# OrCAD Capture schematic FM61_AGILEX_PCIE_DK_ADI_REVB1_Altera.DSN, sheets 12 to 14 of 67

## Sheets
12 DDR4 Single DIMM CH1: size B
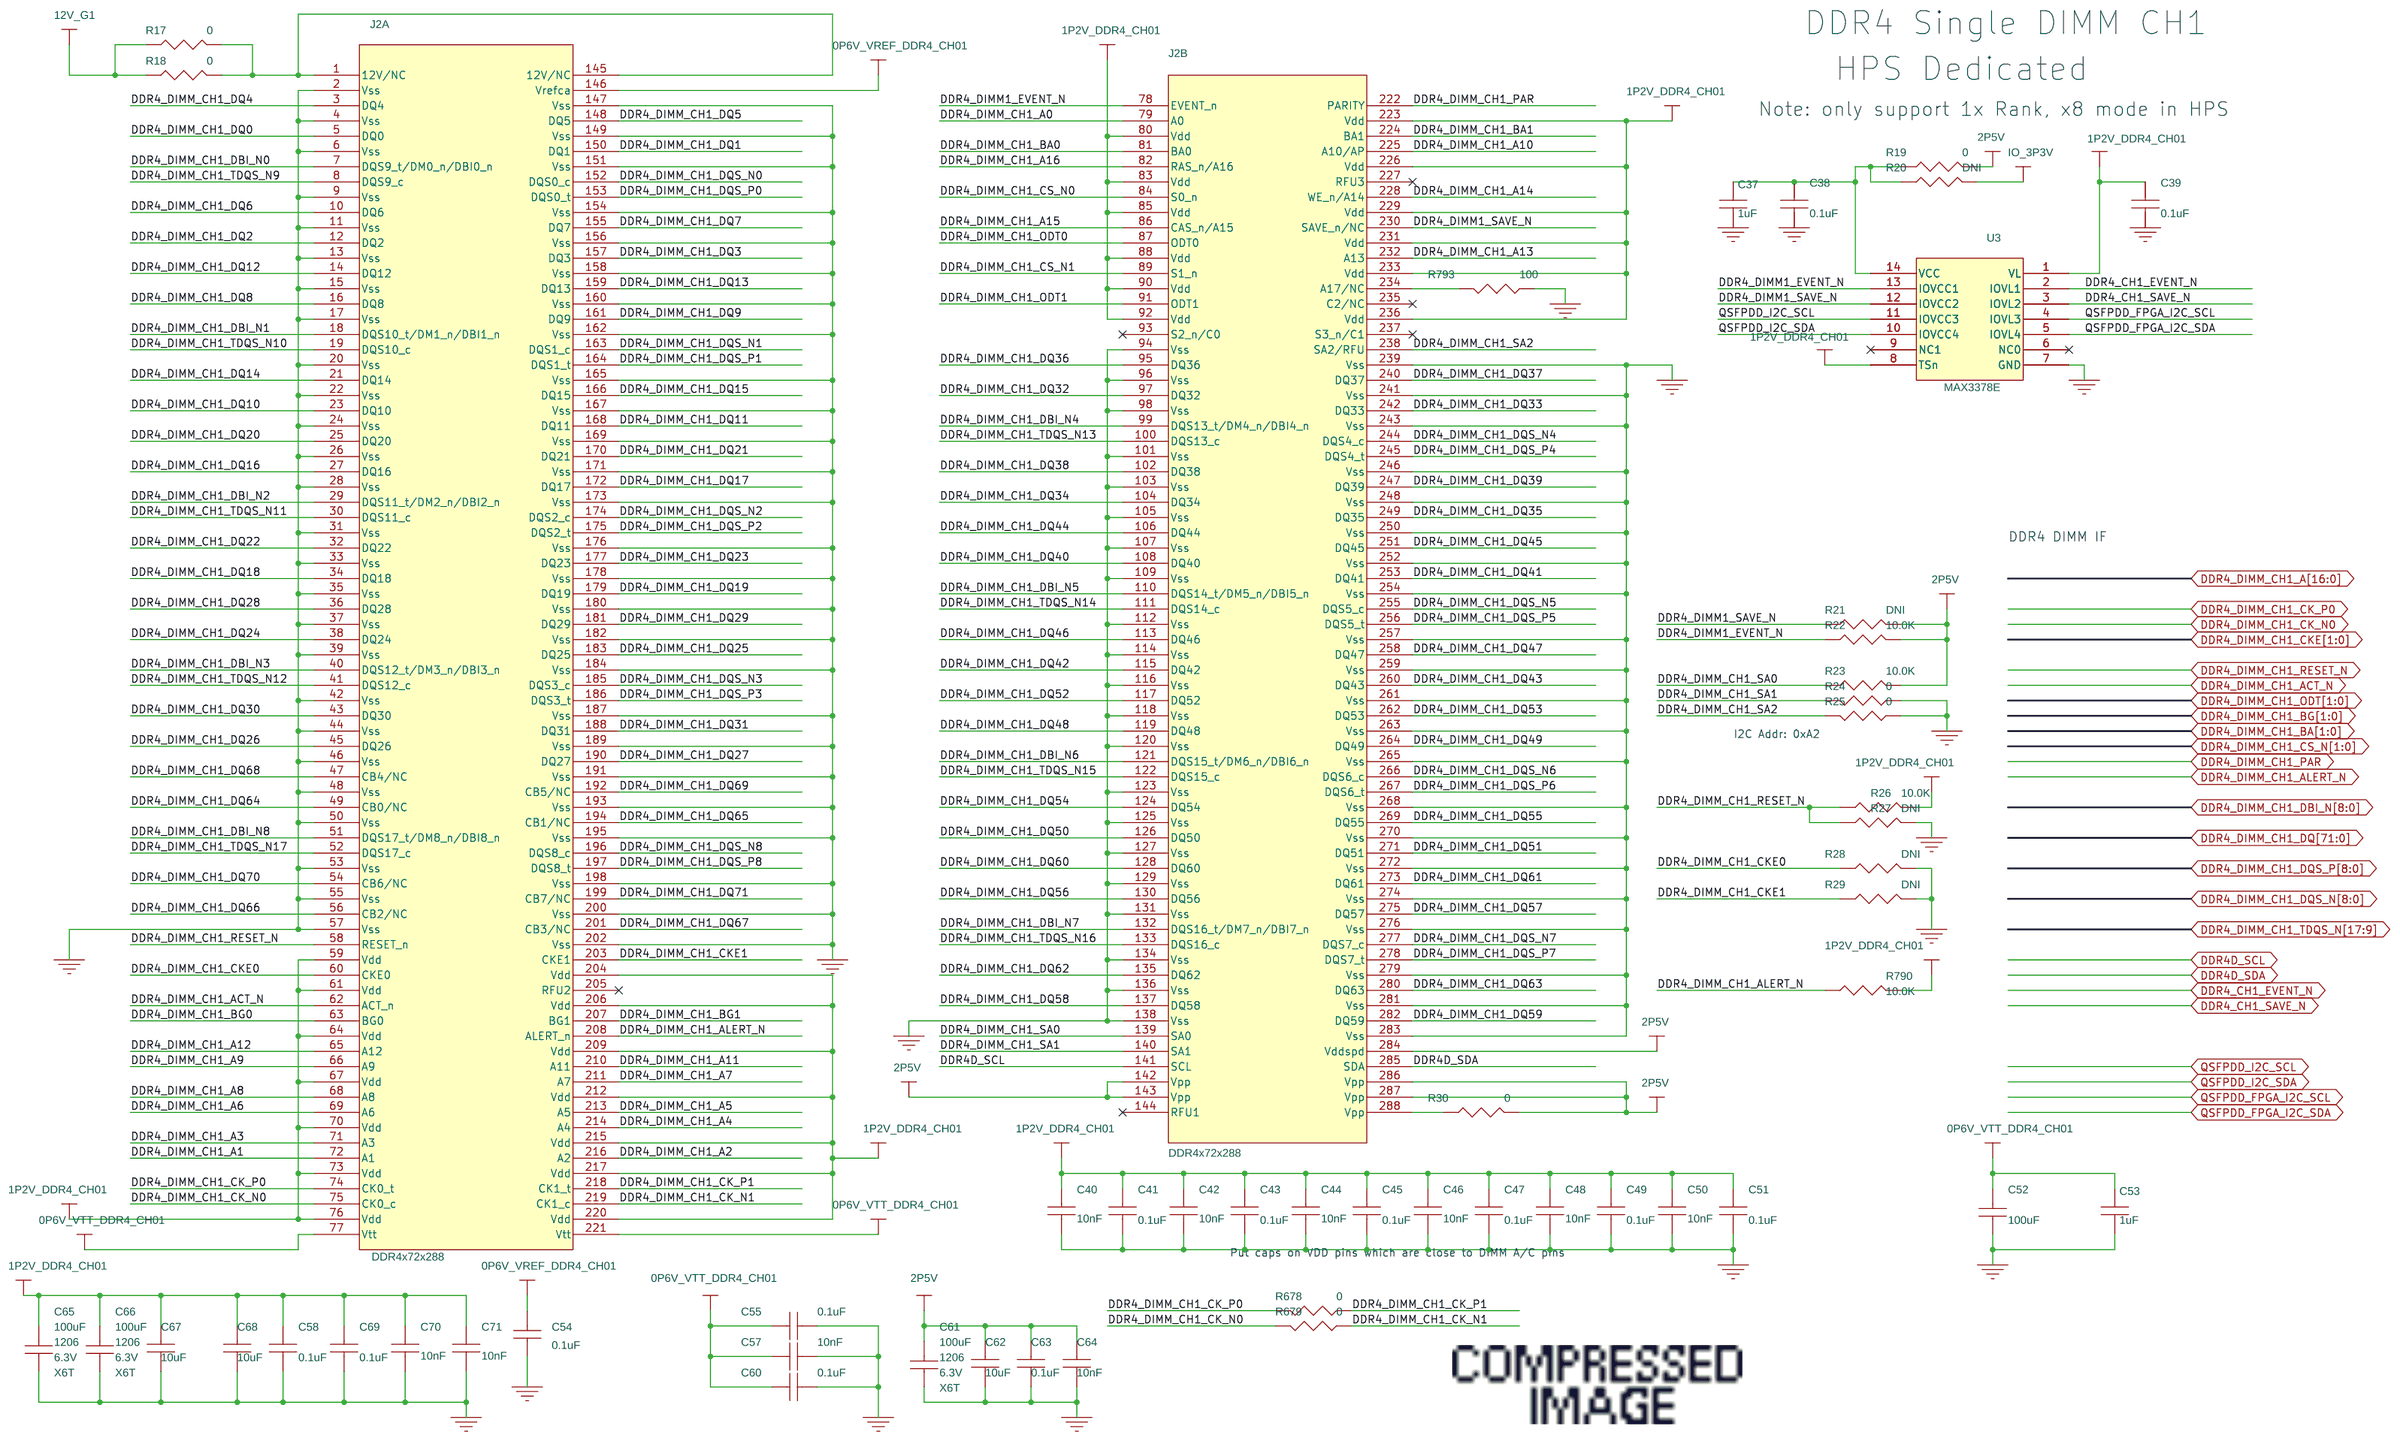
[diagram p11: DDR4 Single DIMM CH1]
13 FPGA BANK 3C: size B
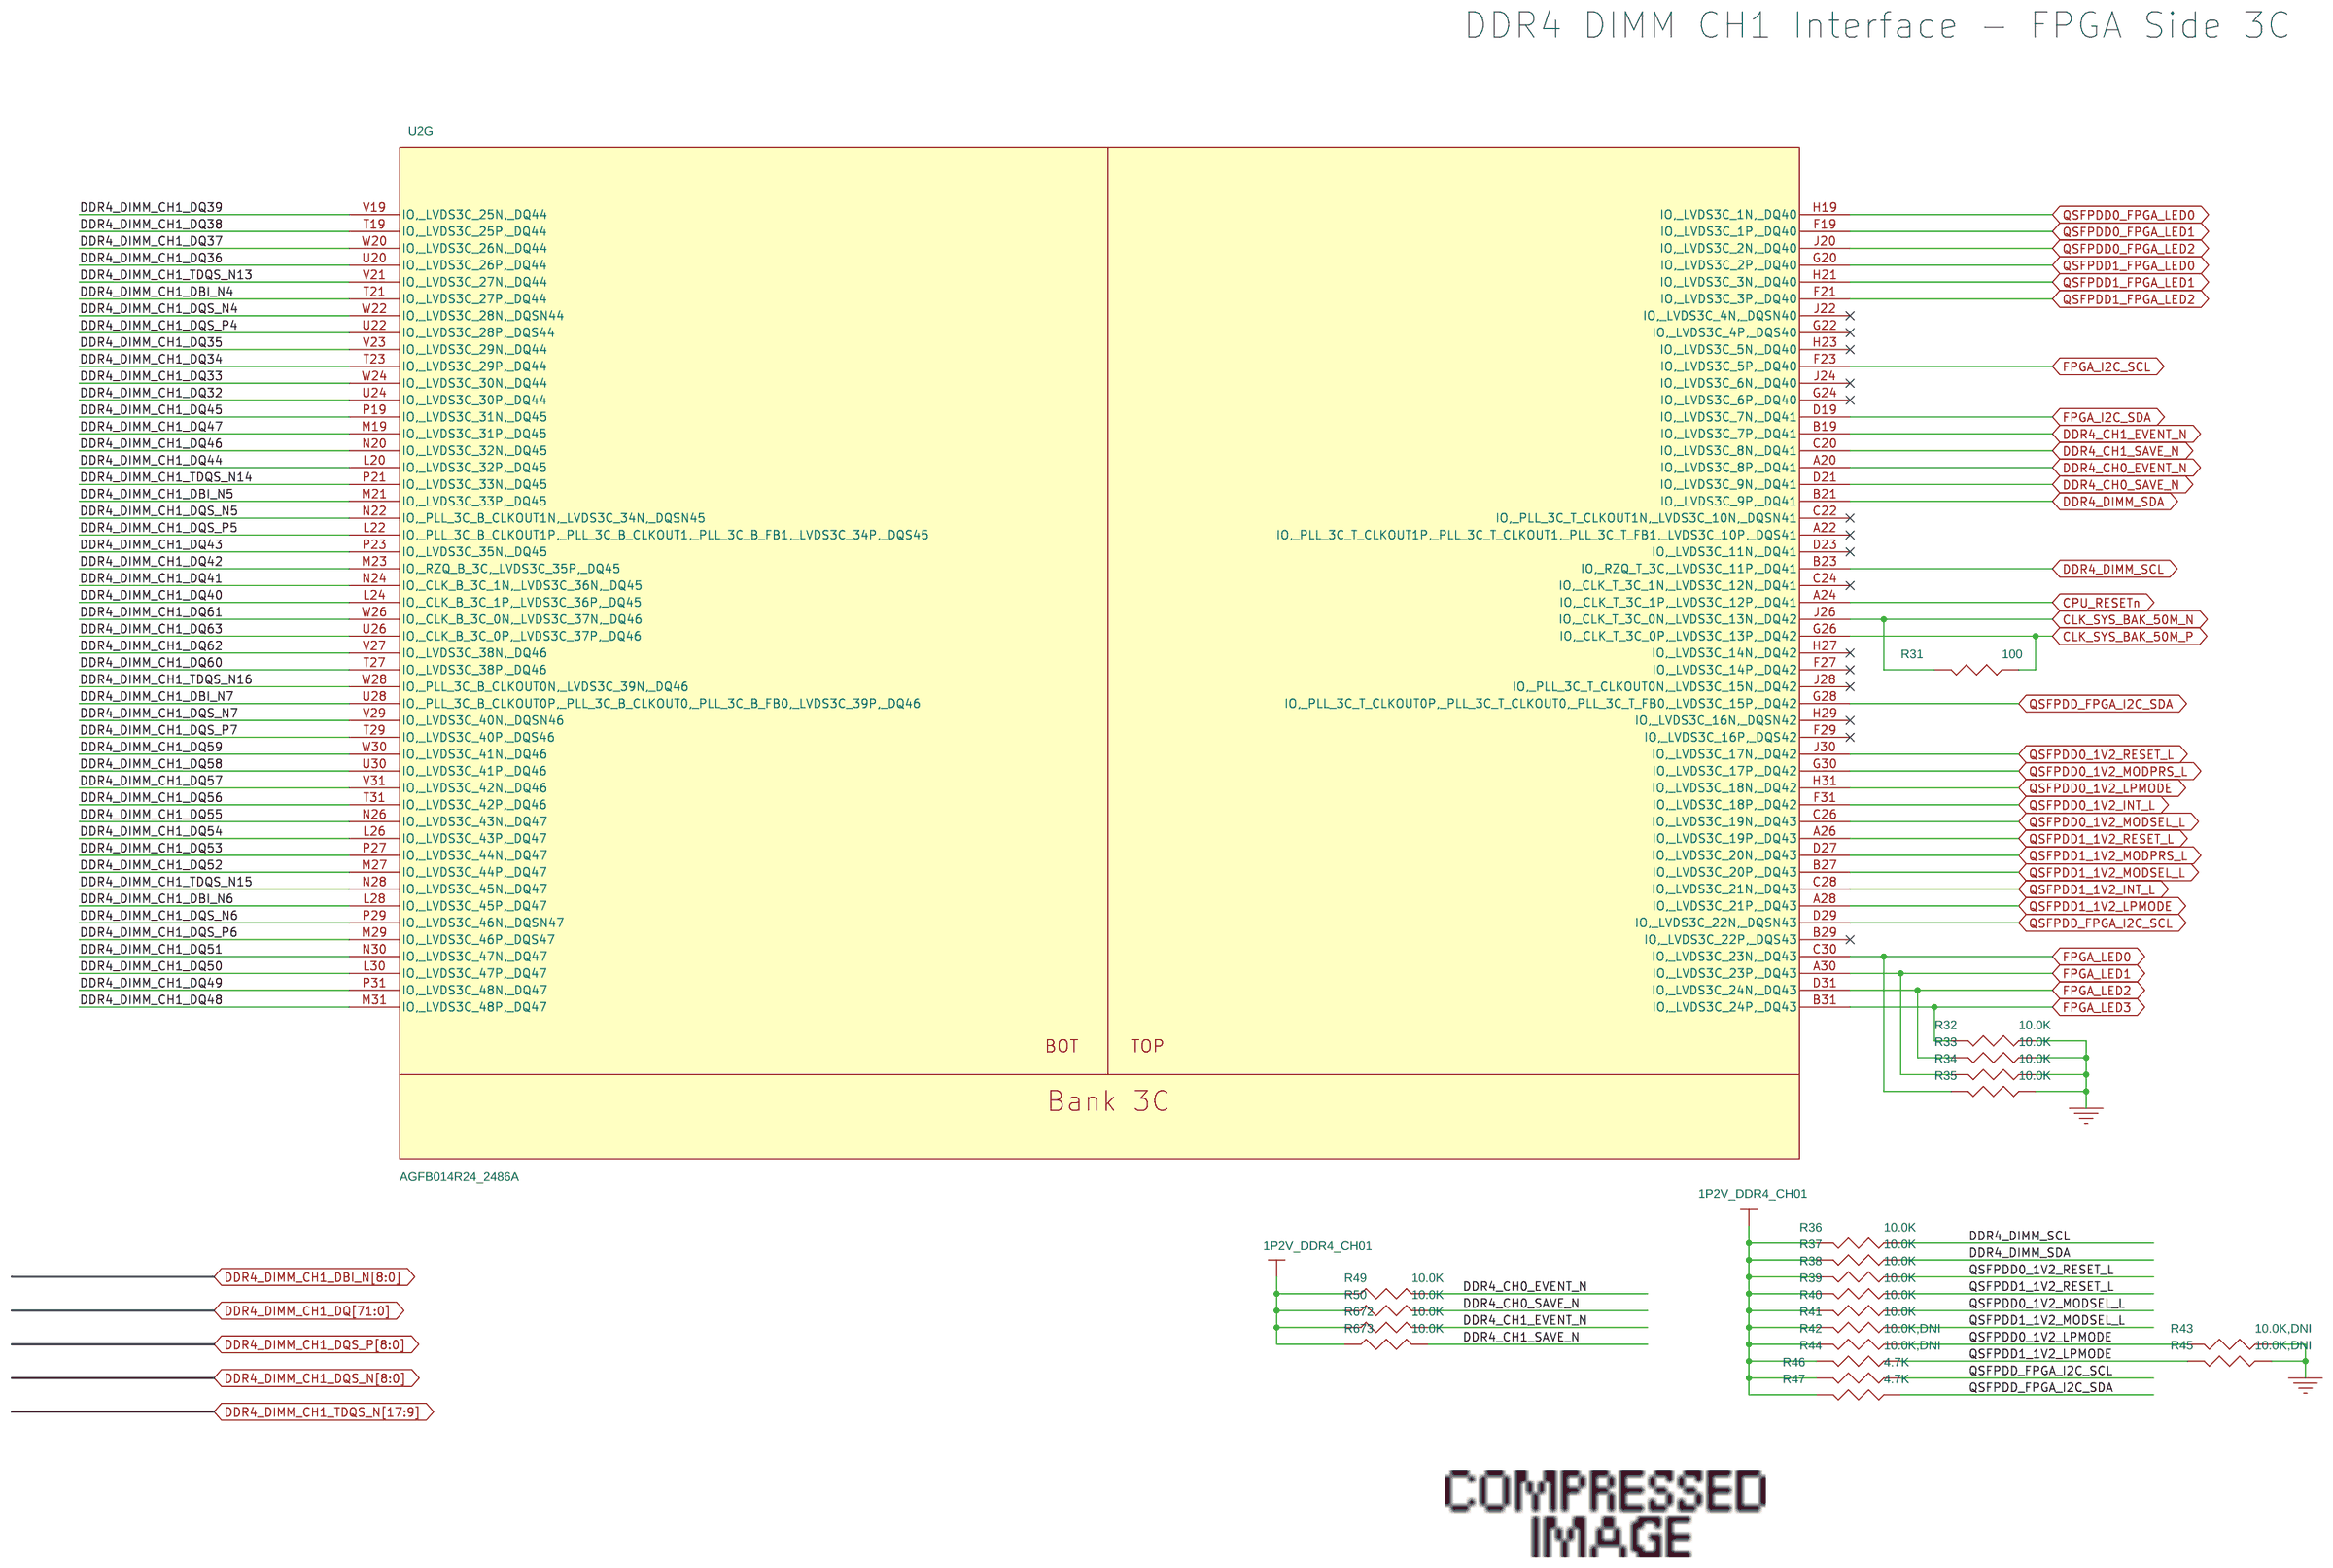
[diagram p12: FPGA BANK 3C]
14 FPGA BANK 3D: size B
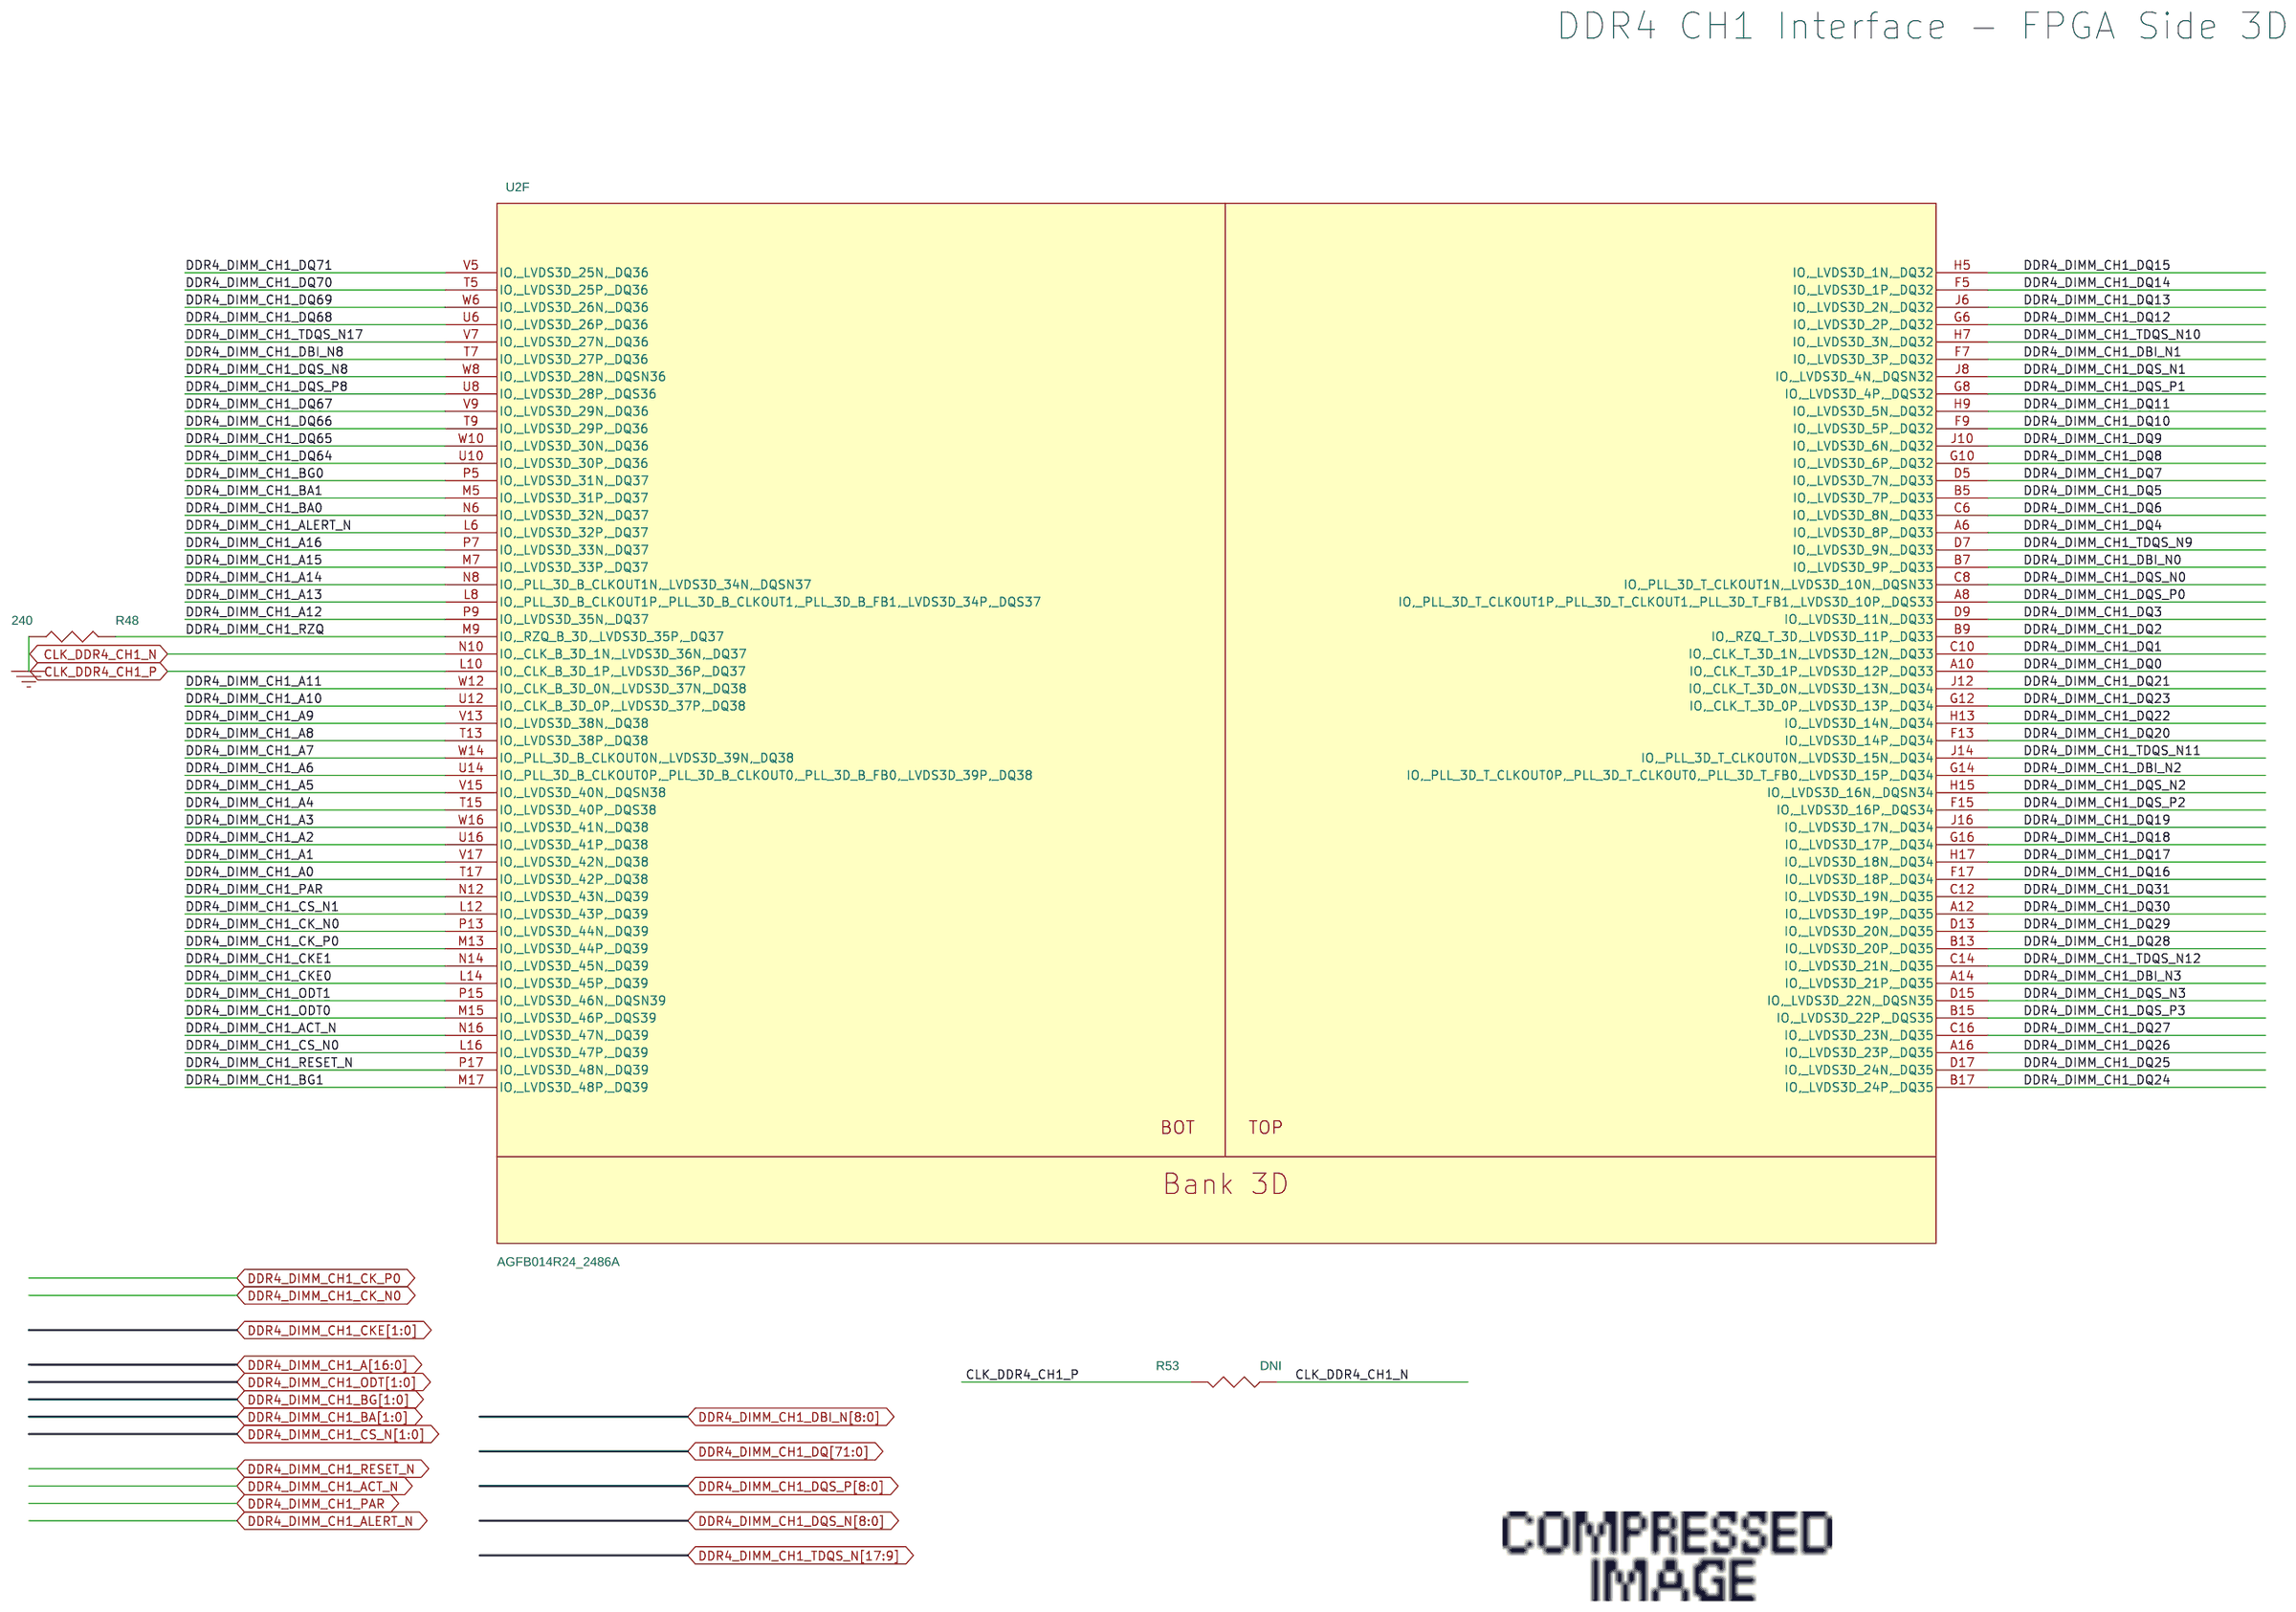
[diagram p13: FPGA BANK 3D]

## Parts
sheet DDR4 Single DIMM CH1
C37  1uF  [0402]
C38  0.1uF  [0402]
C39  0.1uF  [0402]
C40  10nF  [0402]
C41  0.1uF  [0402]
C42  10nF  [0402]
C43  0.1uF  [0402]
C44  10nF  [0402]
C45  0.1uF  [0402]
C46  10nF  [0402]
C47  0.1uF  [0402]
C48  10nF  [0402]
C49  0.1uF  [0402]
C50  10nF  [0402]
C51  0.1uF  [0402]
C52  100uF  [1206]
C53  1uF  [0402]
C54  0.1uF  [0402]
C55  0.1uF  [0402]
C57  10nF  [0402]
C58  0.1uF  [0402]
C60  0.1uF  [0402]
C61  100uF  [1206]
C62  10uF  [1210]
C63  0.1uF  [0402]
C64  10nF  [0402]
C65  100uF  [1206]
C66  100uF  [1206]
C67  10uF  [1210]
C68  10uF  [1210]
C69  0.1uF  [0402]
C70  10nF  [0402]
C71  10nF  [0402]
J2  DDR4x72x288  [DDR4DIMM_SMT]  (sections A,B)
R17  0  [1206]
R18  0  [1206]
R19  0  [0603]
R20  DNI  [0603]
R21  DNI  [0402]
R22  10.0K  [0402]
R23  10.0K  [0402]
R24  0  [0402]
R25  0  [0402]
R26  10.0K  [0402]
R27  DNI  [0402]
R28  DNI  [0402]
R29  DNI  [0402]
R30  0  [0603]
R678  0  [0402]
R679  0  [0402]
R790  10.0K  [0402]
R793  100  [0402]
U3  MAX3378E  [TSSOP-14]
sheet FPGA BANK 3C
R31  100  [0402]
R32  10.0K  [0402]
R33  10.0K  [0402]
R34  10.0K  [0402]
R35  10.0K  [0402]
R36  10.0K  [0402]
R37  10.0K  [0402]
R38  10.0K  [0402]
R39  10.0K  [0402]
R40  10.0K  [0402]
R41  10.0K  [0402]
R42  10.0K,DNI  [0402]
R43  10.0K,DNI  [0402]
R44  10.0K,DNI  [0402]
R45  10.0K,DNI  [0402]
R46  4.7K  [0402]
R47  4.7K  [0402]
R49  10.0K  [0402]
R50  10.0K  [0402]
R672  10.0K  [0402]
R673  10.0K  [0402]
sheet FPGA BANK 3D
R48  240  [0402]
R53  DNI  [0402]
sheet FPGA Gnd 2
U2  AGFB014R24_2486A  [FBGA2486A_HEX]  (sections A,B,C,D,E,F,G,H,I,J,K,L,M,N,O,P,Q,R,S,T,U,V,W,X)

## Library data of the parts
C37 C53 = CAP: CAP, X5R, 1UF, 20%, 10V, 0402,; IPN: H67656-001; Item Num: P03-15479R; Lead Free Status: Yes; Manufacturer: Murata; Manufacturer Part Num: GRM155R61A105KE15D; Num Pins: 2; Part Class: CAPACITORS; RoHS Compliant: Yes; Voltage: 10V
C38 C39 C41 C43 C45 C47 C49 C51 C54 C55 C58 C60 C63 C69 = CAP: CAPC,Y5V,0402,0.1UF,25V,+80/-20%; Dielectric: Y5V; IPN: K13560-001; Item Num: P03-15057R; LIFECYCLE_PHASE: Active; Lead Free Status: Lead Free; MFR_LIFECYCLE: Active; Manufacturer: Murata; Manufacturer Part Num: GRM155F51E104ZA01D; Num Pins: 2; PART_SUBCLASS: CAPACITORS; Part Class: CAPACITORS; RATED_VOLTAGE: 25V; RoHS Compliant: RoHS Compliant; Tolerance: +80%/-20%
C40 C42 C44 C46 C50 C64 C70 C71 = Cap_10000PF_50V_0402: CAP - CERAMIC, 10nF, 0402, 50V, Y5V; IPN: K30697-001; IPN No: K30697-001; Item Num: P03-15058R; Manufacturer Part Num: GRM155F51H103Z
C48 C57 = Cap_10000PF_50V_0402: CAP - CERAMIC, 10nF, 0402, 50V, Y5V; IPN: K30697-001; Item Num: P03-15058R; Manufacturer Part Num: GRM155F51H103Z
C52 C61 C65 C66 = CAP: CAP CER 100UF 6.3V X6T 1206; AGILE_LINK: http://sj-agile9app/Agile/PLMServlet?action=OpenEmailObject&classid=10000&objid=257560276; IPN: H65271-004; Item Num: P03-18002R; LIFECYCLE_PHASE: Active; Lead Free Status: Lead Free; MFR_LIFECYCLE: Active; Manufacturer: Murata; Manufacturer Part Num: GRM31CD80J107ME39L; Num Pins: 2; PART_SUBCLASS: CAPACITORS; RATED_VOLTAGE: 6.3V; RoHS Compliant: RoHS Compliant; TOLERANCE: 20%; Temperature Coefficient: X6T
C62 C67 C68 = CAP_10uF_+_-10%_25V_1210: CAP - CER, 10UF, 25V, 10%, X7R, 1210; Agile Part Description: CAP - CER, 10UF, 25V, 10%, X7R, 1210; IPN: G10603-003; Item Num: P03-15392R; Manufacturer Part Num: GRM32DR71E106KA12L
J2 = DDR4x72x288_1: CONN SMT DDR4 288POS VERT; COMPGROUP: DDR4_PINGPONG_DIMMA; IPN: K21528-001; Item Num: P23-38871R; Manufacturer: Molex Inc; Manufacturer Part Num: 787301002
R17 R18 = RESISTOR: RES SMD 0 OHM JUMPER 3/4W 1206; AGILE_LINK: http://sj-agile9app/Agile/PLMServlet?action=OpenEmailObject&classid=10000&objid=146548997; IPN: A93552-015; Item Num: P02-17994R; LIFECYCLE_PHASE: Active; Lead Free Status: No; MFR_LIFECYCLE: Active; Manufacturer: Vishay Dale; Manufacturer Part Num: CRCW12060000Z0EAHP; Num Pins: 2; PART_SUBCLASS: RESISTORS; POWER: 3/4W; RoHS Compliant: Yes; TOLERANCE: +/-1%
R19 R30 = RESISTOR: RES - 0 OHM, 5% 0603 1/10W; IPN: E57868-001; Item Num: P02-14007R; Lead Free Status: No; Manufacturer: Panasonic; Manufacturer Part Num: ERJ-3GEY0R00V; Num Pins: 2; Part Class: RESISTORS; RoHS Compliant: Yes; Tolerance: 5%
R20 = RESISTOR: RES - 0 OHM, 5% 0603 1/10W; IPN: E57868-001; Item Num: P02-14007R; Lead Free Status: No; Manufacturer: Panasonic; Manufacturer Part Num: ERJ-3GEY0R00V; Num Pins: 2; Part Class: RESISTORS; Price: 0; RoHS Compliant: Yes; Tolerance: 5%
R21 R42-R45 = RESISTOR: RES,10.0K OHMS,1.0%,1/16W, 0402; AGILE_LINK: http://sj-agile9app/Agile/PLMServlet?action=OpenEmailObject&classid=10000&objid=146548997; IPN: A93548-034; Item Num: P02-11364R; LIFECYCLE_PHASE: Active; Lead Free Status: No; MFR_LIFECYCLE: Active; Manufacturer: Panasonic; Manufacturer Part Num: ERJ-2RKF1002X; Num Pins: 2; PART_SUBCLASS: RESISTORS; POWER: 1/16W; RESISTANCE: 10.0K; RoHS Compliant: Yes; TOLERANCE: +/-1%
R22 R23 R26 R32-R41 R49 R50 R672 R673 R790 = RESISTOR: RES,10.0K OHMS,1.0%,1/16W, 0402; AGILE_LINK: http://sj-agile9app/Agile/PLMServlet?action=OpenEmailObject&classid=10000&objid=146548997; IPN: A93548-034; Item Num: P02-11364R; LIFECYCLE_PHASE: Active; Lead Free Status: No; MFR_LIFECYCLE: Active; Manufacturer: Panasonic; Manufacturer Part Num: ERJ-2RKF1002X; Num Pins: 2; PART_SUBCLASS: RESISTORS; POWER: 1/16W; RoHS Compliant: Yes; TOLERANCE: +/-1%
R24 R25 R678 R679 = RES_0_OHM_5%_1_16W_0402_SMD: IPN: H30887-001
R27-R29 = RESISTOR: RES ZERO OHM 1/16W 5% 0402 SMD; IPN: H30887-001; Item Num: P02-14020R; Lead Free Status: No; Manufacturer: Panasonic; Manufacturer Part Num: ERJ-2GE0R00X; Num Pins: 2; Part Class: RESISTORS; Price: 0; RoHS Compliant: Yes; Tolerance: 5%
R31 R53 R793 = RESISTOR: RES,100 OHMS,1.0%,1/16W,0402; IPN: A36092-043; Item Num: P02-11381R; Lead Free Status: No; Manufacturer: Panasonic; Manufacturer Part Num: ERJ-2RKF1000X; Manufacturer's Part No.: ERJ-2RKF1000X; Num Pins: 2; Part Class: RESISTORS; Price: 0; RoHS Compliant: Yes
U3 = MAX3378E_0: IC - QUAD LOW-VOLTAGE LEVEL TRANSLATOR, +/- 15KV, ESD-PROTECTED, 1UA, 16MBPS; IPN: C34337-001; Item Num: P01-13191R; Manufacturer: Maxim; Manufacturer Part Num: MAX3378EEUD
R46 R47 = RESISTOR: RES 4.7K OHM 1/16W 5% 0402 SMD; IPN: H30885-001; Item Num: P02-14032R; Lead Free Status: No; Manufacturer: Panasonic; Manufacturer Part Num: ERJ-2GEJ472X; Manufacturer's Part No.: ERJ-2GEJ472X; Num Pins: 2; Part Class: RESISTORS; Price: 0; RoHS Compliant: Yes
R48 = RESISTOR: RES - 240 OHM, 1/16W, 1%, 0402 SMD; IPN: K15783-001; Item Num: P02-15995R; LIFECYCLE_PHASE: Active; Lead Free Status: Lead Free; MFR_LIFECYCLE: Active; Manufacturer: Panasonic; Manufacturer Part Num: ERJ-2RKF2400X; Num Pins: 2; PART_SUBCLASS: RESISTORS; RoHS Compliant: RoHS Compliant
U2 = FM6_2486A_V1.5: IPN: 99AH52

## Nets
12V_G1: R17.1 R18.1 ; also on sheet 9 15 18 47 48 51 52 53 58
GND: C37.2 C38.2 C39.2 C40.2 C41.2 C42.2 C43.2 C44.2 C45.2 C46.2 C47.2 C48.2 C49.2 C50.2 C51.2 C52.1 C53.2 C54.1 C55.2 C57.2 C58.2 C60.2 C61.1 C62.2 C63.2 C64.2 C65.1 C66.1 C67.2 C68.2 C69.2 C70.2 C71.2 J2.2(Vss) J2.4(Vss) J2.6(Vss) J2.9(Vss) J2.11(Vss) J2.13(Vss) J2.15(Vss) J2.17(Vss) J2.20(Vss) J2.22(Vss) J2.24(Vss) J2.26(Vss) J2.28(Vss) J2.31(Vss) J2.33(Vss) J2.35(Vss) J2.37(Vss) J2.39(Vss) J2.42(Vss) J2.44(Vss) J2.46(Vss) J2.48(Vss) J2.50(Vss) J2.53(Vss) J2.55(Vss) J2.57(Vss) J2.94(Vss) J2.96(Vss) J2.98(Vss) J2.101(Vss) J2.103(Vss) J2.105(Vss) J2.107(Vss) J2.109(Vss) J2.112(Vss) J2.114(Vss) J2.116(Vss) J2.118(Vss) J2.120(Vss) J2.123(Vss) J2.125(Vss) J2.127(Vss) J2.129(Vss) J2.131(Vss) J2.134(Vss) J2.136(Vss) J2.138(Vss) J2.147(Vss) J2.149(Vss) J2.151(Vss) J2.154(Vss) J2.156(Vss) J2.158(Vss) J2.160(Vss) J2.162(Vss) J2.165(Vss) J2.167(Vss) J2.169(Vss) J2.171(Vss) J2.173(Vss) J2.176(Vss) J2.178(Vss) J2.180(Vss) J2.182(Vss) J2.184(Vss) J2.187(Vss) J2.189(Vss) J2.191(Vss) J2.193(Vss) J2.195(Vss) J2.198(Vss) J2.200(Vss) J2.202(Vss) J2.239(Vss) J2.241(Vss) J2.243(Vss) J2.246(Vss) J2.248(Vss) J2.250(Vss) J2.252(Vss) J2.254(Vss) J2.257(Vss) J2.259(Vss) J2.261(Vss) J2.263(Vss) J2.265(Vss) J2.268(Vss) J2.270(Vss) J2.272(Vss) J2.274(Vss) J2.276(Vss) J2.279(Vss) J2.281(Vss) J2.283(Vss) R24.1 R25.1 R27.1 R28.1 R29.1 R32.1 R33.1 R34.1 R35.1 R43.1 R45.1 R48.1 R793.1 U3.7(GND) ; also on sheet 9 11 15 17 18 20 21 22 23 24 25 26 28 29 30 31 32 34 35 36 37 38 39 40 41 42 43 44 45 46 47 48 49 50 51 52 53 54 55 56 57 58 59 60 61 62 63 64 65 66
0p6V_VREF_DDR4_CH01: C54.2 J2.146(Vrefca) ; also on sheet 9 34 62
0p6V_VTT_DDR4_CH01: C52.2 C53.1 C55.1 C57.1 C60.1 J2.77(Vtt) J2.221(Vtt) ; also on sheet 9 62
1p2V_DDR4_CH01: C39.1 C40.1 C41.1 C42.1 C43.1 C44.1 C45.1 C46.1 C47.1 C48.1 C49.1 C50.1 C51.1 C58.1 C65.2 C66.2 C67.1 C68.1 C69.1 C70.1 C71.1 J2.59(Vdd) J2.61(Vdd) J2.64(Vdd) J2.67(Vdd) J2.70(Vdd) J2.73(Vdd) J2.76(Vdd) J2.80(Vdd) J2.83(Vdd) J2.85(Vdd) J2.88(Vdd) J2.90(Vdd) J2.92(Vdd) J2.204(Vdd) J2.206(Vdd) J2.209(Vdd) J2.212(Vdd) J2.215(Vdd) J2.217(Vdd) J2.220(Vdd) J2.223(Vdd) J2.226(Vdd) J2.229(Vdd) J2.231(Vdd) J2.233(Vdd) J2.236(Vdd) R26.2 R36.2 R37.2 R38.2 R39.2 R40.2 R41.2 R42.2 R44.2 R46.2 R47.2 R49.1 R50.1 R672.1 R673.1 R790.2 U3.1(VL) U3.8(TSn) ; also on sheet 9 34 40 42 46 60 62 66
2p5V: C61.2 C62.1 C63.1 C64.1 J2.142(Vpp) J2.143(Vpp) J2.284(Vddspd) J2.286(Vpp) J2.287(Vpp) R19.1 R21.2 R22.2 R23.2 R30.1 ; also on sheet 9 15 18 21 34 38 63
CLK_DDR4_CH1_N: R53.1 U2.N10(IO,_CLK_B_3D_1N,_LVDS3D_36N,_DQ37) ; also on sheet 38
CLK_DDR4_CH1_P: R53.2 U2.L10(IO,_CLK_B_3D_1P,_LVDS3D_36P,_DQ37) ; also on sheet 38
CLK_SYS_BAK_50M_N: R31.2 U2.J26(IO,_CLK_T_3C_0N,_LVDS3C_13N,_DQ42) ; also on sheet 38
CLK_SYS_BAK_50M_P: R31.1 U2.G26(IO,_CLK_T_3C_0P,_LVDS3C_13P,_DQ42) ; also on sheet 38
CPU_RESETn: U2.A24(IO,_CLK_T_3C_1P,_LVDS3C_12P,_DQ41) ; also on sheet 41 44
DDR4_CH0_EVENT_N: R49.2 U2.A20(IO,_LVDS3C_8P,_DQ41) ; also on sheet 9
DDR4_CH0_SAVE_N: R50.2 U2.D21(IO,_LVDS3C_9N,_DQ41) ; also on sheet 9
DDR4_CH1_EVENT_N: R672.2 U2.B19(IO,_LVDS3C_7P,_DQ41) U3.2(IOVL1)
DDR4_CH1_SAVE_N: R673.2 U2.C20(IO,_LVDS3C_8N,_DQ41) U3.3(IOVL2)
DDR4_DIMM1_EVENT_N: J2.78(EVENT_n) R22.1 U3.13(IOVCC1)
DDR4_DIMM1_SAVE_N: J2.230(SAVE_n/NC) R21.1 U3.12(IOVCC2)
DDR4_DIMM_CH1_A0: J2.79(A0) U2.T17(IO,_LVDS3D_42P,_DQ38)
DDR4_DIMM_CH1_A1: J2.72(A1) U2.V17(IO,_LVDS3D_42N,_DQ38)
DDR4_DIMM_CH1_A2: J2.216(A2) U2.U16(IO,_LVDS3D_41P,_DQ38)
DDR4_DIMM_CH1_A3: J2.71(A3) U2.W16(IO,_LVDS3D_41N,_DQ38)
DDR4_DIMM_CH1_A4: J2.214(A4) U2.T15(IO,_LVDS3D_40P,_DQS38)
DDR4_DIMM_CH1_A5: J2.213(A5) U2.V15(IO,_LVDS3D_40N,_DQSN38)
DDR4_DIMM_CH1_A6: J2.69(A6) U2.U14(IO,_PLL_3D_B_CLKOUT0P,_PLL_3D_B_CLKOUT0,_PLL_3D_B_FB0,_LVDS3D_39P,_DQ38)
DDR4_DIMM_CH1_A7: J2.211(A7) U2.W14(IO,_PLL_3D_B_CLKOUT0N,_LVDS3D_39N,_DQ38)
DDR4_DIMM_CH1_A8: J2.68(A8) U2.T13(IO,_LVDS3D_38P,_DQ38)
DDR4_DIMM_CH1_A9: J2.66(A9) U2.V13(IO,_LVDS3D_38N,_DQ38)
DDR4_DIMM_CH1_A10: J2.225(A10/AP) U2.U12(IO,_CLK_B_3D_0P,_LVDS3D_37P,_DQ38)
DDR4_DIMM_CH1_A11: J2.210(A11) U2.W12(IO,_CLK_B_3D_0N,_LVDS3D_37N,_DQ38)
DDR4_DIMM_CH1_A12: J2.65(A12) U2.P9(IO,_LVDS3D_35N,_DQ37)
DDR4_DIMM_CH1_A13: J2.232(A13) U2.L8(IO,_PLL_3D_B_CLKOUT1P,_PLL_3D_B_CLKOUT1,_PLL_3D_B_FB1,_LVDS3D_34P,_DQS37)
DDR4_DIMM_CH1_A14: J2.228(WE_n/A14) U2.N8(IO,_PLL_3D_B_CLKOUT1N,_LVDS3D_34N,_DQSN37)
DDR4_DIMM_CH1_A15: J2.86(CAS_n/A15) U2.M7(IO,_LVDS3D_33P,_DQ37)
DDR4_DIMM_CH1_A16: J2.82(RAS_n/A16) U2.P7(IO,_LVDS3D_33N,_DQ37)
DDR4_DIMM_CH1_ACT_N: J2.62(ACT_n) U2.N16(IO,_LVDS3D_47N,_DQ39)
DDR4_DIMM_CH1_ALERT_N: J2.208(ALERT_n) R790.1 U2.L6(IO,_LVDS3D_32P,_DQ37)
DDR4_DIMM_CH1_BA0: J2.81(BA0) U2.N6(IO,_LVDS3D_32N,_DQ37)
DDR4_DIMM_CH1_BA1: J2.224(BA1) U2.M5(IO,_LVDS3D_31P,_DQ37)
DDR4_DIMM_CH1_BG0: J2.63(BG0) U2.P5(IO,_LVDS3D_31N,_DQ37)
DDR4_DIMM_CH1_BG1: J2.207(BG1) U2.M17(IO,_LVDS3D_48P,_DQ39)
DDR4_DIMM_CH1_CK_N0: J2.75(CK0_c) R679.2 U2.P13(IO,_LVDS3D_44N,_DQ39)
DDR4_DIMM_CH1_CK_N1: J2.219(CK1_c) R679.1
DDR4_DIMM_CH1_CK_P0: J2.74(CK0_t) R678.2 U2.M13(IO,_LVDS3D_44P,_DQ39)
DDR4_DIMM_CH1_CK_P1: J2.218(CK1_t) R678.1
DDR4_DIMM_CH1_CKE0: J2.60(CKE0) R28.2 U2.L14(IO,_LVDS3D_45P,_DQ39)
DDR4_DIMM_CH1_CKE1: J2.203(CKE1) R29.2 U2.N14(IO,_LVDS3D_45N,_DQ39)
DDR4_DIMM_CH1_CS_N0: J2.84(S0_n) U2.L16(IO,_LVDS3D_47P,_DQ39)
DDR4_DIMM_CH1_CS_N1: J2.89(S1_n) U2.L12(IO,_LVDS3D_43P,_DQ39)
DDR4_DIMM_CH1_DBI_N0: J2.7(DQS9_t/DM0_n/DBI0_n) U2.B7(IO,_LVDS3D_9P,_DQ33)
DDR4_DIMM_CH1_DBI_N1: J2.18(DQS10_t/DM1_n/DBI1_n) U2.F7(IO,_LVDS3D_3P,_DQ32)
DDR4_DIMM_CH1_DBI_N2: J2.29(DQS11_t/DM2_n/DBI2_n) U2.G14(IO,_PLL_3D_T_CLKOUT0P,_PLL_3D_T_CLKOUT0,_PLL_3D_T_FB0,_LVDS3D_15P,_DQ34)
DDR4_DIMM_CH1_DBI_N3: J2.40(DQS12_t/DM3_n/DBI3_n) U2.A14(IO,_LVDS3D_21P,_DQ35)
DDR4_DIMM_CH1_DBI_N4: J2.99(DQS13_t/DM4_n/DBI4_n) U2.T21(IO,_LVDS3C_27P,_DQ44)
DDR4_DIMM_CH1_DBI_N5: J2.110(DQS14_t/DM5_n/DBI5_n) U2.M21(IO,_LVDS3C_33P,_DQ45)
DDR4_DIMM_CH1_DBI_N6: J2.121(DQS15_t/DM6_n/DBI6_n) U2.L28(IO,_LVDS3C_45P,_DQ47)
DDR4_DIMM_CH1_DBI_N7: J2.132(DQS16_t/DM7_n/DBI7_n) U2.U28(IO,_PLL_3C_B_CLKOUT0P,_PLL_3C_B_CLKOUT0,_PLL_3C_B_FB0,_LVDS3C_39P,_DQ46)
DDR4_DIMM_CH1_DBI_N8: J2.51(DQS17_t/DM8_n/DBI8_n) U2.T7(IO,_LVDS3D_27P,_DQ36)
DDR4_DIMM_CH1_DQ0: J2.5(DQ0) U2.A10(IO,_CLK_T_3D_1P,_LVDS3D_12P,_DQ33)
DDR4_DIMM_CH1_DQ1: J2.150(DQ1) U2.C10(IO,_CLK_T_3D_1N,_LVDS3D_12N,_DQ33)
DDR4_DIMM_CH1_DQ2: J2.12(DQ2) U2.B9(IO,_RZQ_T_3D,_LVDS3D_11P,_DQ33)
DDR4_DIMM_CH1_DQ3: J2.157(DQ3) U2.D9(IO,_LVDS3D_11N,_DQ33)
DDR4_DIMM_CH1_DQ4: J2.3(DQ4) U2.A6(IO,_LVDS3D_8P,_DQ33)
DDR4_DIMM_CH1_DQ5: J2.148(DQ5) U2.B5(IO,_LVDS3D_7P,_DQ33)
DDR4_DIMM_CH1_DQ6: J2.10(DQ6) U2.C6(IO,_LVDS3D_8N,_DQ33)
DDR4_DIMM_CH1_DQ7: J2.155(DQ7) U2.D5(IO,_LVDS3D_7N,_DQ33)
DDR4_DIMM_CH1_DQ8: J2.16(DQ8) U2.G10(IO,_LVDS3D_6P,_DQ32)
DDR4_DIMM_CH1_DQ9: J2.161(DQ9) U2.J10(IO,_LVDS3D_6N,_DQ32)
DDR4_DIMM_CH1_DQ10: J2.23(DQ10) U2.F9(IO,_LVDS3D_5P,_DQ32)
DDR4_DIMM_CH1_DQ11: J2.168(DQ11) U2.H9(IO,_LVDS3D_5N,_DQ32)
DDR4_DIMM_CH1_DQ12: J2.14(DQ12) U2.G6(IO,_LVDS3D_2P,_DQ32)
DDR4_DIMM_CH1_DQ13: J2.159(DQ13) U2.J6(IO,_LVDS3D_2N,_DQ32)
DDR4_DIMM_CH1_DQ14: J2.21(DQ14) U2.F5(IO,_LVDS3D_1P,_DQ32)
DDR4_DIMM_CH1_DQ15: J2.166(DQ15) U2.H5(IO,_LVDS3D_1N,_DQ32)
DDR4_DIMM_CH1_DQ16: J2.27(DQ16) U2.F17(IO,_LVDS3D_18P,_DQ34)
DDR4_DIMM_CH1_DQ17: J2.172(DQ17) U2.H17(IO,_LVDS3D_18N,_DQ34)
DDR4_DIMM_CH1_DQ18: J2.34(DQ18) U2.G16(IO,_LVDS3D_17P,_DQ34)
DDR4_DIMM_CH1_DQ19: J2.179(DQ19) U2.J16(IO,_LVDS3D_17N,_DQ34)
DDR4_DIMM_CH1_DQ20: J2.25(DQ20) U2.F13(IO,_LVDS3D_14P,_DQ34)
DDR4_DIMM_CH1_DQ21: J2.170(DQ21) U2.J12(IO,_CLK_T_3D_0N,_LVDS3D_13N,_DQ34)
DDR4_DIMM_CH1_DQ22: J2.32(DQ22) U2.H13(IO,_LVDS3D_14N,_DQ34)
DDR4_DIMM_CH1_DQ23: J2.177(DQ23) U2.G12(IO,_CLK_T_3D_0P,_LVDS3D_13P,_DQ34)
DDR4_DIMM_CH1_DQ24: J2.38(DQ24) U2.B17(IO,_LVDS3D_24P,_DQ35)
DDR4_DIMM_CH1_DQ25: J2.183(DQ25) U2.D17(IO,_LVDS3D_24N,_DQ35)
DDR4_DIMM_CH1_DQ26: J2.45(DQ26) U2.A16(IO,_LVDS3D_23P,_DQ35)
DDR4_DIMM_CH1_DQ27: J2.190(DQ27) U2.C16(IO,_LVDS3D_23N,_DQ35)
DDR4_DIMM_CH1_DQ28: J2.36(DQ28) U2.B13(IO,_LVDS3D_20P,_DQ35)
DDR4_DIMM_CH1_DQ29: J2.181(DQ29) U2.D13(IO,_LVDS3D_20N,_DQ35)
DDR4_DIMM_CH1_DQ30: J2.43(DQ30) U2.A12(IO,_LVDS3D_19P,_DQ35)
DDR4_DIMM_CH1_DQ31: J2.188(DQ31) U2.C12(IO,_LVDS3D_19N,_DQ35)
DDR4_DIMM_CH1_DQ32: J2.97(DQ32) U2.U24(IO,_LVDS3C_30P,_DQ44)
DDR4_DIMM_CH1_DQ33: J2.242(DQ33) U2.W24(IO,_LVDS3C_30N,_DQ44)
DDR4_DIMM_CH1_DQ34: J2.104(DQ34) U2.T23(IO,_LVDS3C_29P,_DQ44)
DDR4_DIMM_CH1_DQ35: J2.249(DQ35) U2.V23(IO,_LVDS3C_29N,_DQ44)
DDR4_DIMM_CH1_DQ36: J2.95(DQ36) U2.U20(IO,_LVDS3C_26P,_DQ44)
DDR4_DIMM_CH1_DQ37: J2.240(DQ37) U2.W20(IO,_LVDS3C_26N,_DQ44)
DDR4_DIMM_CH1_DQ38: J2.102(DQ38) U2.T19(IO,_LVDS3C_25P,_DQ44)
DDR4_DIMM_CH1_DQ39: J2.247(DQ39) U2.V19(IO,_LVDS3C_25N,_DQ44)
DDR4_DIMM_CH1_DQ40: J2.108(DQ40) U2.L24(IO,_CLK_B_3C_1P,_LVDS3C_36P,_DQ45)
DDR4_DIMM_CH1_DQ41: J2.253(DQ41) U2.N24(IO,_CLK_B_3C_1N,_LVDS3C_36N,_DQ45)
DDR4_DIMM_CH1_DQ42: J2.115(DQ42) U2.M23(IO,_RZQ_B_3C,_LVDS3C_35P,_DQ45)
DDR4_DIMM_CH1_DQ43: J2.260(DQ43) U2.P23(IO,_LVDS3C_35N,_DQ45)
DDR4_DIMM_CH1_DQ44: J2.106(DQ44) U2.L20(IO,_LVDS3C_32P,_DQ45)
DDR4_DIMM_CH1_DQ45: J2.251(DQ45) U2.P19(IO,_LVDS3C_31N,_DQ45)
DDR4_DIMM_CH1_DQ46: J2.113(DQ46) U2.N20(IO,_LVDS3C_32N,_DQ45)
DDR4_DIMM_CH1_DQ47: J2.258(DQ47) U2.M19(IO,_LVDS3C_31P,_DQ45)
DDR4_DIMM_CH1_DQ48: J2.119(DQ48) U2.M31(IO,_LVDS3C_48P,_DQ47)
DDR4_DIMM_CH1_DQ49: J2.264(DQ49) U2.P31(IO,_LVDS3C_48N,_DQ47)
DDR4_DIMM_CH1_DQ50: J2.126(DQ50) U2.L30(IO,_LVDS3C_47P,_DQ47)
DDR4_DIMM_CH1_DQ51: J2.271(DQ51) U2.N30(IO,_LVDS3C_47N,_DQ47)
DDR4_DIMM_CH1_DQ52: J2.117(DQ52) U2.M27(IO,_LVDS3C_44P,_DQ47)
DDR4_DIMM_CH1_DQ53: J2.262(DQ53) U2.P27(IO,_LVDS3C_44N,_DQ47)
DDR4_DIMM_CH1_DQ54: J2.124(DQ54) U2.L26(IO,_LVDS3C_43P,_DQ47)
DDR4_DIMM_CH1_DQ55: J2.269(DQ55) U2.N26(IO,_LVDS3C_43N,_DQ47)
DDR4_DIMM_CH1_DQ56: J2.130(DQ56) U2.T31(IO,_LVDS3C_42P,_DQ46)
DDR4_DIMM_CH1_DQ57: J2.275(DQ57) U2.V31(IO,_LVDS3C_42N,_DQ46)
DDR4_DIMM_CH1_DQ58: J2.137(DQ58) U2.U30(IO,_LVDS3C_41P,_DQ46)
DDR4_DIMM_CH1_DQ59: J2.282(DQ59) U2.W30(IO,_LVDS3C_41N,_DQ46)
DDR4_DIMM_CH1_DQ60: J2.128(DQ60) U2.T27(IO,_LVDS3C_38P,_DQ46)
DDR4_DIMM_CH1_DQ61: J2.273(DQ61) U2.W26(IO,_CLK_B_3C_0N,_LVDS3C_37N,_DQ46)
DDR4_DIMM_CH1_DQ62: J2.135(DQ62) U2.V27(IO,_LVDS3C_38N,_DQ46)
DDR4_DIMM_CH1_DQ63: J2.280(DQ63) U2.U26(IO,_CLK_B_3C_0P,_LVDS3C_37P,_DQ46)
DDR4_DIMM_CH1_DQ64: J2.49(CB0/NC) U2.U10(IO,_LVDS3D_30P,_DQ36)
DDR4_DIMM_CH1_DQ65: J2.194(CB1/NC) U2.W10(IO,_LVDS3D_30N,_DQ36)
DDR4_DIMM_CH1_DQ66: J2.56(CB2/NC) U2.T9(IO,_LVDS3D_29P,_DQ36)
DDR4_DIMM_CH1_DQ67: J2.201(CB3/NC) U2.V9(IO,_LVDS3D_29N,_DQ36)
DDR4_DIMM_CH1_DQ68: J2.47(CB4/NC) U2.U6(IO,_LVDS3D_26P,_DQ36)
DDR4_DIMM_CH1_DQ69: J2.192(CB5/NC) U2.W6(IO,_LVDS3D_26N,_DQ36)
DDR4_DIMM_CH1_DQ70: J2.54(CB6/NC) U2.T5(IO,_LVDS3D_25P,_DQ36)
DDR4_DIMM_CH1_DQ71: J2.199(CB7/NC) U2.V5(IO,_LVDS3D_25N,_DQ36)
DDR4_DIMM_CH1_DQS_N0: J2.152(DQS0_c) U2.C8(IO,_PLL_3D_T_CLKOUT1N,_LVDS3D_10N,_DQSN33)
DDR4_DIMM_CH1_DQS_N1: J2.163(DQS1_c) U2.J8(IO,_LVDS3D_4N,_DQSN32)
DDR4_DIMM_CH1_DQS_N2: J2.174(DQS2_c) U2.H15(IO,_LVDS3D_16N,_DQSN34)
DDR4_DIMM_CH1_DQS_N3: J2.185(DQS3_c) U2.D15(IO,_LVDS3D_22N,_DQSN35)
DDR4_DIMM_CH1_DQS_N4: J2.244(DQS4_c) U2.W22(IO,_LVDS3C_28N,_DQSN44)
DDR4_DIMM_CH1_DQS_N5: J2.255(DQS5_c) U2.N22(IO,_PLL_3C_B_CLKOUT1N,_LVDS3C_34N,_DQSN45)
DDR4_DIMM_CH1_DQS_N6: J2.266(DQS6_c) U2.P29(IO,_LVDS3C_46N,_DQSN47)
DDR4_DIMM_CH1_DQS_N7: J2.277(DQS7_c) U2.V29(IO,_LVDS3C_40N,_DQSN46)
DDR4_DIMM_CH1_DQS_N8: J2.196(DQS8_c) U2.W8(IO,_LVDS3D_28N,_DQSN36)
DDR4_DIMM_CH1_DQS_P0: J2.153(DQS0_t) U2.A8(IO,_PLL_3D_T_CLKOUT1P,_PLL_3D_T_CLKOUT1,_PLL_3D_T_FB1,_LVDS3D_10P,_DQS33)
DDR4_DIMM_CH1_DQS_P1: J2.164(DQS1_t) U2.G8(IO,_LVDS3D_4P,_DQS32)
DDR4_DIMM_CH1_DQS_P2: J2.175(DQS2_t) U2.F15(IO,_LVDS3D_16P,_DQS34)
DDR4_DIMM_CH1_DQS_P3: J2.186(DQS3_t) U2.B15(IO,_LVDS3D_22P,_DQS35)
DDR4_DIMM_CH1_DQS_P4: J2.245(DQS4_t) U2.U22(IO,_LVDS3C_28P,_DQS44)
DDR4_DIMM_CH1_DQS_P5: J2.256(DQS5_t) U2.L22(IO,_PLL_3C_B_CLKOUT1P,_PLL_3C_B_CLKOUT1,_PLL_3C_B_FB1,_LVDS3C_34P,_DQS45)
DDR4_DIMM_CH1_DQS_P6: J2.267(DQS6_t) U2.M29(IO,_LVDS3C_46P,_DQS47)
DDR4_DIMM_CH1_DQS_P7: J2.278(DQS7_t) U2.T29(IO,_LVDS3C_40P,_DQS46)
DDR4_DIMM_CH1_DQS_P8: J2.197(DQS8_t) U2.U8(IO,_LVDS3D_28P,_DQS36)
DDR4_DIMM_CH1_ODT0: J2.87(ODT0) U2.M15(IO,_LVDS3D_46P,_DQS39)
DDR4_DIMM_CH1_ODT1: J2.91(ODT1) U2.P15(IO,_LVDS3D_46N,_DQSN39)
DDR4_DIMM_CH1_PAR: J2.222(PARITY) U2.N12(IO,_LVDS3D_43N,_DQ39)
DDR4_DIMM_CH1_RESET_N: J2.58(RESET_n) R26.1 R27.2 U2.P17(IO,_LVDS3D_48N,_DQ39)
DDR4_DIMM_CH1_RZQ: R48.2 U2.M9(IO,_RZQ_B_3D,_LVDS3D_35P,_DQ37)
DDR4_DIMM_CH1_SA0: J2.139(SA0) R23.1
DDR4_DIMM_CH1_SA1: J2.140(SA1) R24.2
DDR4_DIMM_CH1_SA2: J2.238(SA2/RFU) R25.2
DDR4_DIMM_CH1_TDQS_N9: J2.8(DQS9_c) U2.D7(IO,_LVDS3D_9N,_DQ33)
DDR4_DIMM_CH1_TDQS_N10: J2.19(DQS10_c) U2.H7(IO,_LVDS3D_3N,_DQ32)
DDR4_DIMM_CH1_TDQS_N11: J2.30(DQS11_c) U2.J14(IO,_PLL_3D_T_CLKOUT0N,_LVDS3D_15N,_DQ34)
DDR4_DIMM_CH1_TDQS_N12: J2.41(DQS12_c) U2.C14(IO,_LVDS3D_21N,_DQ35)
DDR4_DIMM_CH1_TDQS_N13: J2.100(DQS13_c) U2.V21(IO,_LVDS3C_27N,_DQ44)
DDR4_DIMM_CH1_TDQS_N14: J2.111(DQS14_c) U2.P21(IO,_LVDS3C_33N,_DQ45)
DDR4_DIMM_CH1_TDQS_N15: J2.122(DQS15_c) U2.N28(IO,_LVDS3C_45N,_DQ47)
DDR4_DIMM_CH1_TDQS_N16: J2.133(DQS16_c) U2.W28(IO,_PLL_3C_B_CLKOUT0N,_LVDS3C_39N,_DQ46)
DDR4_DIMM_CH1_TDQS_N17: J2.52(DQS17_c) U2.V7(IO,_LVDS3D_27N,_DQ36)
DDR4_DIMM_SCL: R36.1 U2.B23(IO,_RZQ_T_3C,_LVDS3C_11P,_DQ41) ; also on sheet 9
DDR4_DIMM_SDA: R37.1 U2.B21(IO,_LVDS3C_9P,_DQ41) ; also on sheet 9
DDR4D_SCL: J2.141(SCL) ; also on sheet 9 15 18
DDR4D_SDA: J2.285(SDA) ; also on sheet 9 15 18
FPGA_I2C_SCL: U2.F23(IO,_LVDS3C_5P,_DQ40) ; also on sheet 40
FPGA_I2C_SDA: U2.D19(IO,_LVDS3C_7N,_DQ41) ; also on sheet 40
FPGA_LED0: R35.2 U2.C30(IO,_LVDS3C_23N,_DQ43) ; also on sheet 44
FPGA_LED1: R34.2 U2.A30(IO,_LVDS3C_23P,_DQ43) ; also on sheet 44
FPGA_LED2: R33.2 U2.D31(IO,_LVDS3C_24N,_DQ43) ; also on sheet 44
FPGA_LED3: R32.2 U2.B31(IO,_LVDS3C_24P,_DQ43) ; also on sheet 44
IO_3p3V: R20.1 ; also on sheet 23 24 25 28 30 31 38 39 40 41 42 63
QSFPDD0_1V2_INT_L: U2.F31(IO,_LVDS3C_18P,_DQ42) ; also on sheet 44
QSFPDD0_1V2_LPMODE: R42.1 R43.2 U2.H31(IO,_LVDS3C_18N,_DQ42) ; also on sheet 44
QSFPDD0_1V2_MODPRS_L: U2.G30(IO,_LVDS3C_17P,_DQ42) ; also on sheet 44
QSFPDD0_1V2_MODSEL_L: R40.1 U2.C26(IO,_LVDS3C_19N,_DQ43) ; also on sheet 44
QSFPDD0_1V2_RESET_L: R38.1 U2.J30(IO,_LVDS3C_17N,_DQ42) ; also on sheet 44
QSFPDD0_FPGA_LED0: U2.H19(IO,_LVDS3C_1N,_DQ40) ; also on sheet 42
QSFPDD0_FPGA_LED1: U2.F19(IO,_LVDS3C_1P,_DQ40) ; also on sheet 42
QSFPDD0_FPGA_LED2: U2.J20(IO,_LVDS3C_2N,_DQ40) ; also on sheet 42
QSFPDD1_1V2_INT_L: U2.C28(IO,_LVDS3C_21N,_DQ43) ; also on sheet 44
QSFPDD1_1V2_LPMODE: R44.1 R45.2 U2.A28(IO,_LVDS3C_21P,_DQ43) ; also on sheet 44
QSFPDD1_1V2_MODPRS_L: U2.D27(IO,_LVDS3C_20N,_DQ43) ; also on sheet 44
QSFPDD1_1V2_MODSEL_L: R41.1 U2.B27(IO,_LVDS3C_20P,_DQ43) ; also on sheet 44
QSFPDD1_1V2_RESET_L: R39.1 U2.A26(IO,_LVDS3C_19P,_DQ43) ; also on sheet 44
QSFPDD1_FPGA_LED0: U2.G20(IO,_LVDS3C_2P,_DQ40) ; also on sheet 42
QSFPDD1_FPGA_LED1: U2.H21(IO,_LVDS3C_3N,_DQ40) ; also on sheet 42
QSFPDD1_FPGA_LED2: U2.F21(IO,_LVDS3C_3P,_DQ40) ; also on sheet 42
QSFPDD_FPGA_I2C_SCL: R46.1 U2.D29(IO,_LVDS3C_22N,_DQSN43) U3.4(IOVL3)
QSFPDD_FPGA_I2C_SDA: R47.1 U2.G28(IO,_PLL_3C_T_CLKOUT0P,_PLL_3C_T_CLKOUT0,_PLL_3C_T_FB0,_LVDS3C_15P,_DQ42) U3.5(IOVL4)
QSFPDD_I2C_SCL: U3.11(IOVCC3) ; also on sheet 23 24
QSFPDD_I2C_SDA: U3.10(IOVCC4) ; also on sheet 23 24
N42744699: J2.1(12V/NC) J2.145(12V/NC) R17.2 R18.2
N42745155: C37.1 C38.1 R19.2 R20.2 U3.14(VCC)
N42745359: J2.234(A17/NC) R793.2
N42746504: J2.288(Vpp) R30.2

Not connected (* = marked no-connect by the designer): J2 93(S2_n/C0)* 144(RFU1)* 205(RFU2)* 227(RFU3)* 235(C2/NC)* 237(S3_n/C1)*; U2 A22(IO,_PLL_3C_T_CLKOUT1P,_PLL_3C_T_CLKOUT1,_PLL_3C_T_FB1,_LVDS3C_10P,_DQS41)* B29(IO,_LVDS3C_22P,_DQS43)* C22(IO,_PLL_3C_T_CLKOUT1N,_LVDS3C_10N,_DQSN41)* C24(IO,_CLK_T_3C_1N,_LVDS3C_12N,_DQ41)* D23(IO,_LVDS3C_11N,_DQ41)* F27(IO,_LVDS3C_14P,_DQ42)* F29(IO,_LVDS3C_16P,_DQS42)* G22(IO,_LVDS3C_4P,_DQS40)* G24(IO,_LVDS3C_6P,_DQ40)* H23(IO,_LVDS3C_5N,_DQ40)* H27(IO,_LVDS3C_14N,_DQ42)* H29(IO,_LVDS3C_16N,_DQSN42)* J22(IO,_LVDS3C_4N,_DQSN40)* J24(IO,_LVDS3C_6N,_DQ40)* J28(IO,_PLL_3C_T_CLKOUT0N,_LVDS3C_15N,_DQ42)*; U3 6(NC0)* 9(NC1)*

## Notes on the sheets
sheet 12
- DDR4 Single DIMM CH1
- HPS Dedicated
- Note: only support 1x Rank, x8 mode in HPS
- DDR4 DIMM IF
- I2C Addr: 0xA2
- Put caps on VDD pins which are close to DIMM A/C pins
sheet 13
- DDR4 DIMM CH1 Interface - FPGA Side 3C
sheet 14
- DDR4 CH1 Interface - FPGA Side 3D
